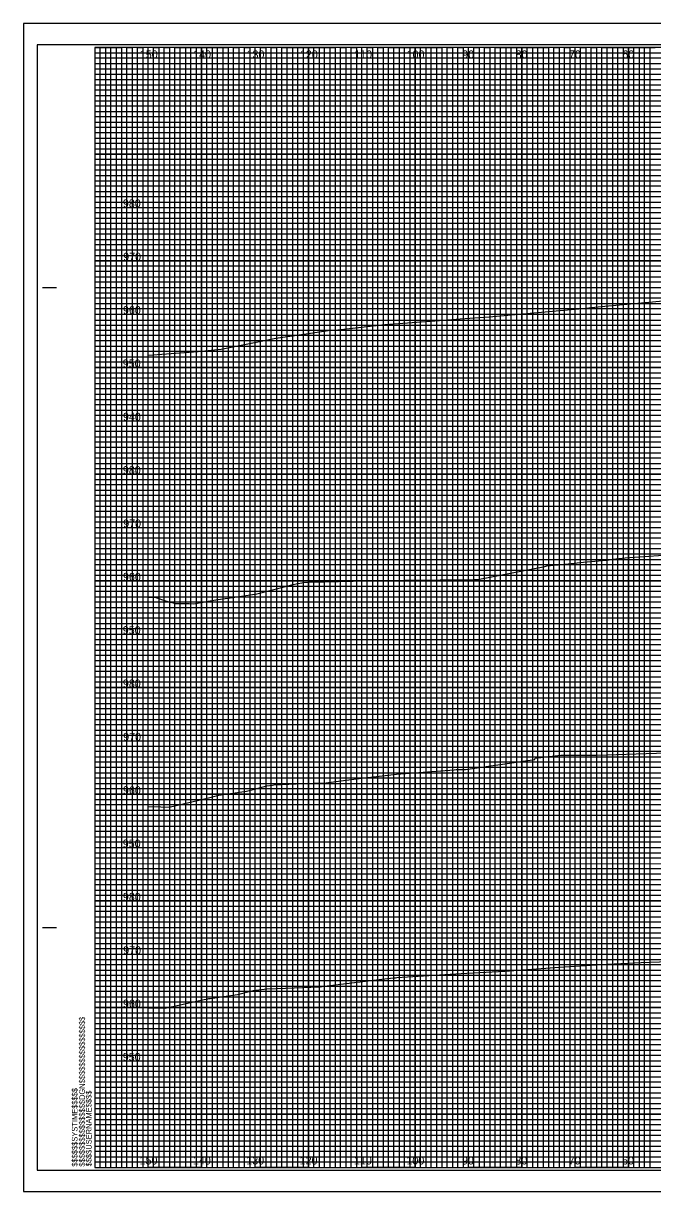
# Model space of a CAD drawing. Extents: x -13 to 760, y -5 to 1491.
# Drawn here: x -13.4 to 104.5, y 633.5 to 852.5 of the extents above; entities that cross this region are included whole.
import ezdxf

# ---------------------------------------------------------------- set-up
doc = ezdxf.new("R2010")
doc.units = 0
for name, color, linetype in [('Default', 7, 'Continuous'), ('Exist XS Ground Line', 7, 'Continuous'), ('Prop XS Elevation Labels', 7, 'Continuous'), ('Prop XS Offset Labels', 7, 'Continuous'), ('Sheet Cross Section CELL', 7, 'Continuous'), ('Sheet Cross Section Grid Major CELL', 7, 'Continuous'), ('Sheet Cross Section Grid Middle CELL', 7, 'Continuous'), ('Sheet Cross Section Grid Minor 1 CELL', 7, 'Continuous'), ('Sheet Cross Section Grid Minor 2 CELL', 7, 'Continuous'), ('Sheet Cutting Line CELL', 7, 'Continuous'), ('Sheet DOT Grid CELL', 7, 'Continuous'), ('Sheet Plot Border Inside CELL', 7, 'Continuous'), ('Sheet Plot Border Outside CELL', 7, 'Continuous')]:
    doc.layers.add(name, color=color, linetype=linetype)

msp = doc.modelspace()

# ---------------------------------------------------------------- linework, layer by layer
at = {"layer": 'Exist XS Ground Line'}
for points in [[(10, 790.32), (13.41, 790.54), (19.32, 791.03), (23.65, 791.43), (32.41, 793.19), (33.88, 793.49), (39.16, 794.25), (44.12, 794.98), (45.5, 795.09), (54.35, 796.06), (58.58, 796.38), (64.59, 796.83), (68.44, 797.11), (73.86, 797.51), (78.73, 797.95), (91.39, 799.07), (94.84, 799.42), (103.78, 800.25), (115.68, 801.38)], [(10, 790.32), (13.41, 790.54), (19.32, 791.03), (23.65, 791.43), (32.41, 793.19), (33.88, 793.49), (39.16, 794.25), (44.12, 794.98), (45.5, 795.09), (54.35, 796.06), (58.58, 796.38), (64.59, 796.83), (68.44, 797.11), (73.86, 797.51), (78.73, 797.95), (91.39, 799.07), (94.84, 799.42), (103.78, 800.25), (115.68, 801.38)], [(10, 744.92), (11.41, 744.86), (13.2, 744.29), (15.09, 743.78), (17.68, 743.73), (18.5, 743.71), (20.64, 744.09), (21.23, 744.19), (22.67, 744.43), (26.63, 745.03), (30.36, 745.59), (35.71, 746.96), (37.16, 747.33), (37.7, 747.43), (39.14, 747.71), (40.11, 747.75), (53.97, 748.09), (57.87, 748.14), (58.43, 748.14), (70.95, 748.24), (71.68, 748.25), (71.75, 748.25), (84.3, 750.72), (84.66, 750.79), (87.51, 751.06), (91.54, 751.53), (95.8, 751.9), (96.36, 751.95), (96.4, 751.98), (99.36, 752.3), (106.45, 752.83)], [(10, 744.92), (11.41, 744.86), (13.2, 744.29), (15.09, 743.78), (17.68, 743.73), (18.5, 743.71), (20.64, 744.09), (21.23, 744.19), (22.67, 744.43), (26.63, 745.03), (30.36, 745.59), (35.71, 746.96), (37.16, 747.33), (37.7, 747.43), (39.14, 747.71), (40.11, 747.75), (53.97, 748.09), (57.87, 748.14), (58.43, 748.14), (70.95, 748.24), (71.68, 748.25), (71.75, 748.25), (84.3, 750.72), (84.66, 750.79), (87.51, 751.06), (91.54, 751.53), (95.8, 751.9), (96.36, 751.95), (96.4, 751.98), (99.36, 752.3), (106.45, 752.83)], [(10, 705.71), (12.33, 705.63), (13.93, 705.57), (17.6, 706.48), (20.52, 707.13), (23.2, 707.8), (24.94, 708.08), (28.38, 708.6), (29.92, 708.97), (32.19, 709.55), (33.27, 709.7), (33.52, 709.75), (37.74, 709.96), (38.42, 710), (38.87, 710.01), (43.36, 710.14), (44.69, 710.34), (47.1, 710.67), (48.51, 710.83), (50.54, 711.09), (51.12, 711.16), (56.49, 711.79), (67.29, 712.59), (67.72, 712.64), (69.42, 712.64), (82.44, 714.53), (82.49, 714.74), (87.33, 715.3), (88.56, 715.32), (88.91, 715.35), (91.4, 715.31), (91.67, 715.31), (94.06, 715.32), (101.42, 715.57), (107.12, 715.75)], [(10, 705.71), (12.33, 705.63), (13.93, 705.57), (17.6, 706.48), (20.52, 707.13), (23.2, 707.8), (24.94, 708.08), (28.38, 708.6), (29.92, 708.97), (32.19, 709.55), (33.27, 709.7), (33.52, 709.75), (37.74, 709.96), (38.42, 710), (38.87, 710.01), (43.36, 710.14), (44.69, 710.34), (47.1, 710.67), (48.51, 710.83), (50.54, 711.09), (51.12, 711.16), (56.49, 711.79), (67.29, 712.59), (67.72, 712.64), (69.42, 712.64), (82.44, 714.53), (82.49, 714.74), (87.33, 715.3), (88.56, 715.32), (88.91, 715.35), (91.4, 715.31), (91.67, 715.31), (94.06, 715.32), (101.42, 715.57), (107.12, 715.75)], [(10, 667.99), (13.17, 667.89), (20.49, 669.52), (20.97, 669.61), (21.34, 669.7), (21.59, 669.74), (26.75, 670.48), (29.66, 671.19), (29.87, 671.24), (30.2, 671.29), (32.19, 671.54), (35.74, 671.65), (37.31, 671.72), (40.45, 671.86), (42.18, 671.93), (43.01, 672.05), (53.27, 673.25), (55.9, 673.56), (56.33, 673.6), (56.6, 673.62), (66.56, 674.26), (69.68, 674.44), (76.8, 674.85), (82.77, 675.25), (87.03, 675.6), (95.86, 676.15), (97.27, 676.24), (102.33, 676.46), (107.5, 676.64)], [(10, 667.99), (13.17, 667.89), (20.49, 669.52), (20.97, 669.61), (21.34, 669.7), (21.59, 669.74), (26.75, 670.48), (29.66, 671.19), (29.87, 671.24), (30.2, 671.29), (32.19, 671.54), (35.74, 671.65), (37.31, 671.72), (40.45, 671.86), (42.18, 671.93), (43.01, 672.05), (53.27, 673.25), (55.9, 673.56), (56.33, 673.6), (56.6, 673.62), (66.56, 674.26), (69.68, 674.44), (76.8, 674.85), (82.77, 675.25), (87.03, 675.6), (95.86, 676.15), (97.27, 676.24), (102.33, 676.46), (107.5, 676.64)]]:
    msp.add_lwpolyline(points, dxfattribs=at)
at = {"layer": 'Sheet Cross Section CELL'}
for p, q in [((-9.8, 803.01), (-7.3, 803.01)), ((-9.7, 803.01), (-7.2, 803.01)), ((-9.8, 683.01), (-7.3, 683.01)), ((-9.7, 683.01), (-7.2, 683.01)), ((0, 638.01), (0, 638.01)), ((0, 638.01), (0, 638.01)), ((0, 638.01), (0, 638.01)), ((0, 638.01), (0, 638.01)), ((0, 638.01), (0, 638.01)), ((0, 638.01), (0, 638.01)), ((0, 638.01), (0, 638.01))]:
    msp.add_line(p, q, dxfattribs=at)
msp.add_lwpolyline([(320, 848.01), (0, 848.01), (0, 638.01), (320, 638.01)], close=True, dxfattribs=at)
at = {"layer": 'Sheet Cross Section Grid Major CELL'}
for p, q in [((10, 848.01), (0, 848.01)), ((10, 638.01), (10, 848.01)), ((30, 848.01), (20, 848.01)), ((20, 848.01), (20, 638.01)), ((30, 638.01), (30, 848.01)), ((50, 848.01), (40, 848.01)), ((40, 848.01), (40, 638.01)), ((50, 638.01), (50, 848.01)), ((70, 848.01), (60, 848.01)), ((60, 848.01), (60, 638.01)), ((70, 638.01), (70, 848.01)), ((90, 848.01), (80, 848.01)), ((80, 848.01), (80, 638.01)), ((90, 638.01), (90, 848.01)), ((110, 848.01), (100, 848.01)), ((100, 848.01), (100, 638.01)), ((20, 638.01), (10, 638.01)), ((40, 638.01), (30, 638.01)), ((60, 638.01), (50, 638.01)), ((80, 638.01), (70, 638.01)), ((100, 638.01), (90, 638.01))]:
    msp.add_line(p, q, dxfattribs=at)
for points in [[(0, 838.01), (320, 838.01), (320, 828.01), (0, 828.01)], [(0, 818.01), (320, 818.01), (320, 808.01), (0, 808.01)], [(0, 798.01), (320, 798.01), (320, 788.01), (0, 788.01)], [(0, 778.01), (320, 778.01), (320, 768.01), (0, 768.01)], [(0, 758.01), (320, 758.01), (320, 748.01), (0, 748.01)], [(0, 738.01), (320, 738.01), (320, 728.01), (0, 728.01)], [(0, 718.01), (320, 718.01), (320, 708.01), (0, 708.01)], [(0, 698.01), (320, 698.01), (320, 688.01), (0, 688.01)], [(0, 678.01), (320, 678.01), (320, 668.01), (0, 668.01)], [(0, 658.01), (320, 658.01), (320, 648.01), (0, 648.01)]]:
    msp.add_lwpolyline(points, dxfattribs=at)
at = {"layer": 'Sheet Cross Section Grid Middle CELL'}
for points in [[(0, 848.01), (5, 848.01), (5, 638.01), (15, 638.01), (15, 848.01), (25, 848.01), (25, 638.01), (35, 638.01), (35, 848.01), (45, 848.01), (45, 638.01), (55, 638.01), (55, 848.01), (65, 848.01), (65, 638.01), (75, 638.01), (75, 848.01), (85, 848.01), (85, 638.01), (95, 638.01), (95, 848.01), (105, 848.01)], [(0, 843.01), (275, 843.01)], [(0, 823.01), (320, 823.01), (320, 833.01), (0, 833.01)], [(0, 803.01), (320, 803.01), (320, 813.01), (0, 813.01)], [(0, 783.01), (320, 783.01), (320, 793.01), (0, 793.01)], [(0, 763.01), (320, 763.01), (320, 773.01), (0, 773.01)], [(0, 743.01), (320, 743.01), (320, 753.01), (0, 753.01)], [(0, 723.01), (320, 723.01), (320, 733.01), (0, 733.01)], [(0, 703.01), (320, 703.01), (320, 713.01), (0, 713.01)], [(0, 683.01), (320, 683.01), (320, 693.01), (0, 693.01)], [(0, 663.01), (320, 663.01), (320, 673.01), (0, 673.01)], [(0, 643.01), (320, 643.01), (320, 653.01), (0, 653.01)]]:
    msp.add_lwpolyline(points, dxfattribs=at)
at = {"layer": 'Sheet Cross Section Grid Minor 1 CELL'}
for p, q in [((0, 847.01), (260, 847.01)), ((260, 845.99), (0, 845.99)), ((0, 845.99), (0, 845.01)), ((0, 845.01), (260, 845.01)), ((260, 843.9), (0, 843.9)), ((0, 843.9), (0, 842.01)), ((0, 842.01), (320, 842.01))]:
    msp.add_line(p, q, dxfattribs=at)
for points in [[(0, 841.01), (270, 841.01), (320, 841.01), (320, 840.01), (0, 840.01)], [(0, 839.01), (320, 839.01), (320, 837.01), (0, 837.01)], [(0, 836.01), (320, 836.01), (320, 835.01), (0, 834.99)], [(0, 834.01), (320, 834.01), (320, 832.01), (0, 832.01)], [(0, 831.01), (320, 831.01), (320, 830.01), (0, 830.01)], [(0, 829.01), (320, 829.01), (320, 827.01), (0, 827.01)], [(0, 826.01), (320, 826.01), (320, 825.01), (0, 825.01)], [(0, 824.01), (320, 824.01), (320, 822.01), (0, 822.01)], [(0, 821.01), (320, 821.01), (320, 820.01), (0, 820.01)], [(0, 819.01), (320, 819.01), (320, 817.01), (0, 817.01)], [(0, 816.01), (320, 816.01), (320, 815.01), (0, 815.01)], [(0, 814.01), (320, 814.01), (320, 811.96), (320, 811.01), (320, 810.01), (0, 810.01)], [(0, 812.01), (320, 812.01), (320, 811.01), (0, 811.01)], [(0, 809.01), (320, 809.01), (320, 807.01), (0, 807.04)], [(0, 807.04), (320, 807.01), (320, 806.01), (0, 806.01)], [(0, 805.01), (320, 805.01), (320, 804.01), (0, 804.01)], [(0, 802.01), (320, 802.01), (320, 801.01), (0, 801.01)], [(0, 800.01), (320, 800.01), (320, 799.01), (0, 799.01)], [(-0.07, 796.9), (320, 796.9), (320, 795.89), (-0.07, 795.89)], [(0, 795.01), (320, 795.01), (320, 794.01), (0, 794.01)], [(0, 792.01), (320, 792.01), (320, 791.01), (0, 791.01)], [(0, 790.01), (320, 790.01), (320, 789.01), (0, 789.01)], [(0, 787.01), (320, 787.01), (320, 786.01), (0, 786.01)], [(0, 785.01), (320, 785.01), (320, 784.01), (0, 784.01)], [(0, 782.01), (320, 782.01), (320, 781.01), (0, 781.01)], [(0, 780.01), (320, 780.01), (320, 779.01), (0, 779.01)], [(0, 777.01), (320, 777.01), (319.99, 775.99), (0, 776.01)], [(0, 775.01), (320, 775.01), (320, 774.01), (0, 774.01)], [(0, 772.01), (320, 772.01), (320, 771.01), (0, 771.01)], [(0, 770.01), (320, 770.01), (320, 769.01), (0, 769.01)], [(0, 767.01), (320, 767.01), (320, 766.01), (0, 766.01)], [(0, 765.01), (320, 765.01), (320, 764.01), (0, 764.01)], [(0, 762.01), (320, 762.01), (320, 761.01), (0, 761.01)], [(0, 760.01), (320, 760.01), (320, 759.01), (0, 759.01)], [(0, 757.01), (320, 757.01), (320, 756.01), (0, 756.01)], [(0, 755), (320.07, 754.92), (320, 754.01), (0, 754.01)], [(0, 752.01), (320, 752.01), (320, 751.01), (0, 751.01)], [(0, 750.01), (320, 750.01), (320, 749.01), (0, 749.01)], [(0, 747.01), (320, 747.01), (320, 746.01), (0, 746.01)], [(0, 745.01), (320, 745.01), (320, 744.01), (0, 744.01)], [(0, 742.01), (320, 742.01), (320, 741.01), (0, 741.01)], [(0, 740.01), (320, 740.01), (320, 739.01), (0, 739.01)], [(0, 737.01), (320, 737.01), (320, 736.01), (0, 736.01)], [(0, 735.01), (320, 735.01), (320, 734.01), (0, 734.01)], [(0, 732.01), (320, 732.01), (320, 731.01), (0, 731.01)], [(0, 730.01), (320, 730.01), (320, 729.01), (0, 729.01)], [(0, 727.01), (320, 727.01), (320, 726.01), (0, 726.01)], [(0, 725.01), (320, 725.01), (320, 724.01), (0, 724.01)], [(0, 722.01), (320, 722.01), (320, 721.01), (0, 721.01)], [(0, 720.01), (320, 720.01), (320, 719.01), (0, 719.01)], [(0, 717.01), (320, 717.01), (319.99, 715.99), (0, 716.01)], [(0, 715.01), (320, 715.01), (320, 714.01), (0, 714.01)], [(0, 712.01), (320, 712.01), (320, 711.01), (0, 711.01)], [(0, 710.01), (320, 710.01), (320, 709.01), (0, 709.01)], [(0, 707.01), (320, 707.01), (320, 706.01), (0, 706.01)], [(0, 705.01), (320, 705.01), (320, 704.01), (0, 704.01)], [(0, 702.01), (320, 702.01), (320, 701.01), (0, 701.01)], [(0, 700.01), (320, 700.01), (320, 699.01), (0, 699.01)], [(0, 697.01), (320, 697.01), (320, 696.01), (0, 696.01)], [(0, 695), (320.07, 694.92), (320, 694.01), (0, 694.01)], [(0, 692.01), (320, 692.01), (320, 691.01), (0, 691.01)], [(0, 690.01), (320, 690.01), (320, 689.01), (0, 689.01)], [(0, 687.01), (320, 687.01), (320, 686.01), (0, 686.01)], [(0, 685.01), (320, 685.01), (320, 684.01), (0, 684.01)], [(0, 682.01), (320, 682.01), (320, 681.01), (0, 681.01)], [(0, 680.01), (320, 680.01), (320, 679.01), (0, 679.01)], [(0, 677.01), (320, 677.01), (320, 676.01), (0, 676.01)], [(0, 675.01), (320, 675.01), (320, 674.01), (0, 674.01)], [(0, 672.01), (320, 672.01), (320, 671.01), (0, 671.01)], [(0, 670.01), (320, 670.01), (320, 669.01), (0, 669.01)], [(0, 667.01), (320, 667.01), (320, 666.01), (0, 666.01)], [(0, 665.01), (320, 665.01), (320, 664.01), (0, 664.01)], [(0, 662.01), (320, 662.01), (320, 661.01), (0, 661.01)], [(0, 660.01), (320, 660.01), (320, 659.01), (0, 659.01)], [(0, 657.01), (320, 657.01), (320, 656.01), (0, 656.01)], [(0, 655.01), (320, 655.01), (320, 654.01), (0, 654.01)], [(0, 652.01), (320, 652.01), (320, 651.01), (0, 651.01)], [(0, 650.01), (320, 650.01), (320, 649.01), (0, 649.01)], [(0, 647.01), (320, 647.01), (320, 646.01), (0, 646.01)], [(0, 645.01), (320, 645.01), (320, 644.01), (0, 644.01)], [(0, 642.01), (320, 642.01), (320, 641.01), (0, 641.01)], [(0, 640.01), (320, 640.01), (320, 639.01), (0, 639.01)]]:
    msp.add_lwpolyline(points, dxfattribs=at)
at = {"layer": 'Sheet Cross Section Grid Minor 2 CELL'}
for points in [[(0, 638.01), (1, 638.01), (1, 848.01), (2, 848.01), (2, 638.01)], [(2, 638.01), (3, 638.01), (3, 848.01), (4, 848.01), (4, 638.01)], [(5, 638.01), (6, 638.01), (6, 848.01), (7, 848.01), (7, 638.01)], [(7, 638.01), (8, 638.01), (8, 848.01), (9, 848.01), (9, 638.01)], [(10, 638.01), (11, 638.01), (11, 848.01), (12, 848.01), (12, 638.01)], [(12, 638.01), (13, 638.01), (13, 848.01), (14, 848.01), (14, 638.01)], [(15, 638.01), (16, 638.01), (16, 848.01), (17, 848.01), (17, 638.01)], [(17, 638.01), (18, 638.01), (18, 848.01), (19, 848.01), (19, 638.01)], [(20, 638.01), (21, 638.01), (21, 848.01), (22, 848.01), (22, 638.01)], [(22, 638.01), (23, 638.01), (23, 848.01), (24, 848.01), (24, 638.01)], [(25, 638.01), (26, 638.01), (26, 848.01), (27, 848.01), (27, 638.01)], [(27, 638.01), (28, 638.01), (28, 848.01), (29, 848.01), (29, 638.01)], [(30, 638.01), (31, 638.01), (31, 848.01), (32, 848.01), (32, 638.01)], [(32, 638.01), (33, 638.01), (33, 848.01), (34, 848.01), (34, 638.01)], [(35, 638.01), (36, 638.01), (36, 848.01), (37, 848.01), (37, 638.01)], [(37, 638.01), (38, 638.01), (38, 848.01), (39, 848.01), (39, 638.01)], [(40, 638.01), (41, 638.01), (41, 848.01), (42, 848.01), (42, 638.01)], [(42, 638.01), (43, 638.01), (43, 848.01), (44, 848.01), (44, 638.01)], [(45, 638.01), (46, 638.01), (46, 848.01), (47, 848.01), (47, 638.01)], [(47, 638.01), (48, 638.01), (48, 848.01), (49, 848.01), (49, 638.01)], [(50, 638.01), (51, 638.01), (51, 848.01), (52, 848.01), (52, 638.01)], [(52, 638.01), (53, 638.01), (53, 848.01), (54, 848.01), (54, 638.01)], [(55, 638.01), (56, 638.01), (56, 848.01), (57, 848.01), (57, 638.01)], [(57, 638.01), (58, 638.01), (58, 848.01), (59, 848.01), (59, 638.01)], [(60, 638.01), (61, 638.01), (61, 848.01), (62, 848.01), (62, 638.01)], [(62, 638.01), (63, 638.01), (63, 848.01), (64, 848.01), (64, 638.01)], [(65, 638.01), (66, 638.01), (66, 848.01), (67, 848.01), (67, 638.01)], [(67, 638.01), (68, 638.01), (68, 848.01), (69, 848.01), (69, 638.01)], [(70, 638.01), (71, 638.01), (71, 848.01), (72, 848.01), (72, 638.01)], [(72, 638.01), (73, 638.01), (73, 848.01), (74, 848.01), (74, 638.01)], [(75, 638.01), (76, 638.01), (76, 848.01), (77, 848.01), (77, 638.01)], [(77, 638.01), (78, 638.01), (78, 848.01), (79, 848.01), (79, 638.01)], [(80, 638.01), (81, 638.01), (81, 848.01), (82, 848.01), (82, 638.01)], [(82, 638.01), (83, 638.01), (83, 848.01), (84, 848.01), (84, 638.01)], [(85, 638.01), (86, 638.01), (86, 848.01), (87, 848.01), (87, 638.01)], [(87, 638.01), (88, 638.01), (88, 848.01), (89, 848.01), (89, 638.01)], [(90, 638.01), (91, 638.01), (91, 848.01), (92, 848.01), (92, 638.01)], [(92, 638.01), (93, 638.01), (93, 848.01), (94, 848.01), (94, 638.01)], [(95, 638.01), (96, 638.01), (96, 848.01), (97, 848.01), (97, 638.01)], [(97, 638.01), (98, 638.01), (98, 848.01), (99, 848.01), (99, 638.01)], [(100, 638.01), (101, 638.01), (101, 848.01), (102, 848.01), (102, 638.01)], [(102, 638.01), (103, 638.01), (103, 848.01), (104, 848.01), (104, 638.01)]]:
    msp.add_lwpolyline(points, dxfattribs=at)
at = {"layer": 'Sheet Cutting Line CELL'}
for p, q in [((323.3, 852.51), (-13.4, 852.51)), ((-13.4, 852.51), (-13.4, 633.51)), ((-13.4, 633.51), (323.3, 633.51))]:
    msp.add_line(p, q, dxfattribs=at)
at = {"layer": 'Sheet DOT Grid CELL'}
for p, q in [((10, 638.01), (10, 848.01)), ((20, 638.01), (20, 848.01)), ((30, 638.01), (30, 848.01)), ((40, 638.01), (40, 848.01)), ((50, 638.01), (50, 848.01)), ((60, 638.01), (60, 848.01)), ((70, 638.01), (70, 848.01)), ((80, 638.01), (80, 848.01)), ((90, 638.01), (90, 848.01)), ((100, 638.01), (100, 848.01)), ((0, 838.01), (320, 838.01)), ((0, 828.01), (320, 828.01)), ((0, 818.01), (320, 818.01)), ((0, 808.01), (320, 808.01)), ((0, 798.01), (320, 798.01)), ((0, 788.01), (320, 788.01)), ((0, 778.01), (320, 778.01)), ((0, 768.01), (320, 768.01)), ((0, 758.01), (320, 758.01)), ((0, 748.01), (320, 748.01)), ((0, 738.01), (320, 738.01)), ((0, 728.01), (320, 728.01)), ((0, 718.01), (320, 718.01)), ((0, 708.01), (320, 708.01)), ((0, 698.01), (320, 698.01)), ((0, 688.01), (320, 688.01)), ((0, 678.01), (320, 678.01)), ((0, 668.01), (320, 668.01)), ((0, 658.01), (320, 658.01)), ((0, 648.01), (320, 648.01))]:
    msp.add_line(p, q, dxfattribs=at)
at = {"layer": 'Sheet Plot Border Inside CELL'}
msp.add_lwpolyline([(-10.8, 637.51), (322.4, 637.51), (322.4, 848.51), (-10.8, 848.51)], close=True, dxfattribs=at)
at = {"layer": 'Sheet Plot Border Outside CELL'}
msp.add_lwpolyline([(-13.4, 633.51), (323.3, 633.51), (323.3, 852.51), (-13.4, 852.51)], close=True, dxfattribs=at)

# ---------------------------------------------------------------- texts
at = {"layer": 'Default'}
for p in [(10, 778.01), (10, 738.01), (10, 698.01), (10, 658.01)]:
    msp.add_text('-', height=0.0001, dxfattribs=at).set_placement(p)
at = {"layer": 'Prop XS Elevation Labels'}
for s, p in [('980', (5.24, 818.01)), ('970', (5.3, 808.01)), ('960', (5.26, 798.01)), ('950', (5.22, 788.01)), ('940', (5.26, 778.01)), ('980', (5.24, 768.01)), ('970', (5.3, 758.01)), ('960', (5.26, 748.01)), ('950', (5.22, 738.01)), ('980', (5.24, 728.01)), ('970', (5.3, 718.01)), ('960', (5.26, 708.01)), ('950', (5.22, 698.01)), ('980', (5.24, 688.01)), ('970', (5.3, 678.01)), ('960', (5.26, 668.01)), ('950', (5.22, 658.01))]:
    msp.add_text(s, height=1.5, dxfattribs=at).set_placement(p)
at = {"layer": 'Prop XS Offset Labels'}
for s, p in [('150', (8.41, 845.94)), ('140', (18.41, 845.94)), ('130', (28.41, 845.94)), ('120', (38.41, 845.94)), ('110', (48.59, 845.94)), ('100', (58.41, 845.94)), ('90', (68.83, 845.94)), ('80', (78.83, 845.94)), ('70', (88.83, 845.94)), ('60', (98.83, 845.94)), ('150', (8.37, 638.6)), ('140', (18.37, 638.6)), ('130', (28.37, 638.6)), ('120', (38.37, 638.6)), ('110', (48.55, 638.6)), ('100', (58.37, 638.6)), ('90', (68.78, 638.6)), ('80', (78.78, 638.6)), ('70', (88.78, 638.6)), ('60', (98.78, 638.6))]:
    msp.add_text(s, height=1.5, dxfattribs=at).set_placement(p)
at = {"layer": 'Sheet Cross Section CELL'}
for s, p in [('$$$$$$$$$$$$$$$$DGN$$$$$$$$$$$$$$$$', (-1.88, 638.19)), ('$$$$$$SYSTIME$$$$$', (-3.26, 638.19)), ('$$$$USERNAME$$$$', (-0.62, 638.24))]:
    msp.add_text(s, height=1.05, rotation=90, dxfattribs=at).set_placement(p)

doc.saveas('drawing.dxf')
